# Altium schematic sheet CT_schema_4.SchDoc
size 485 x 464 mm
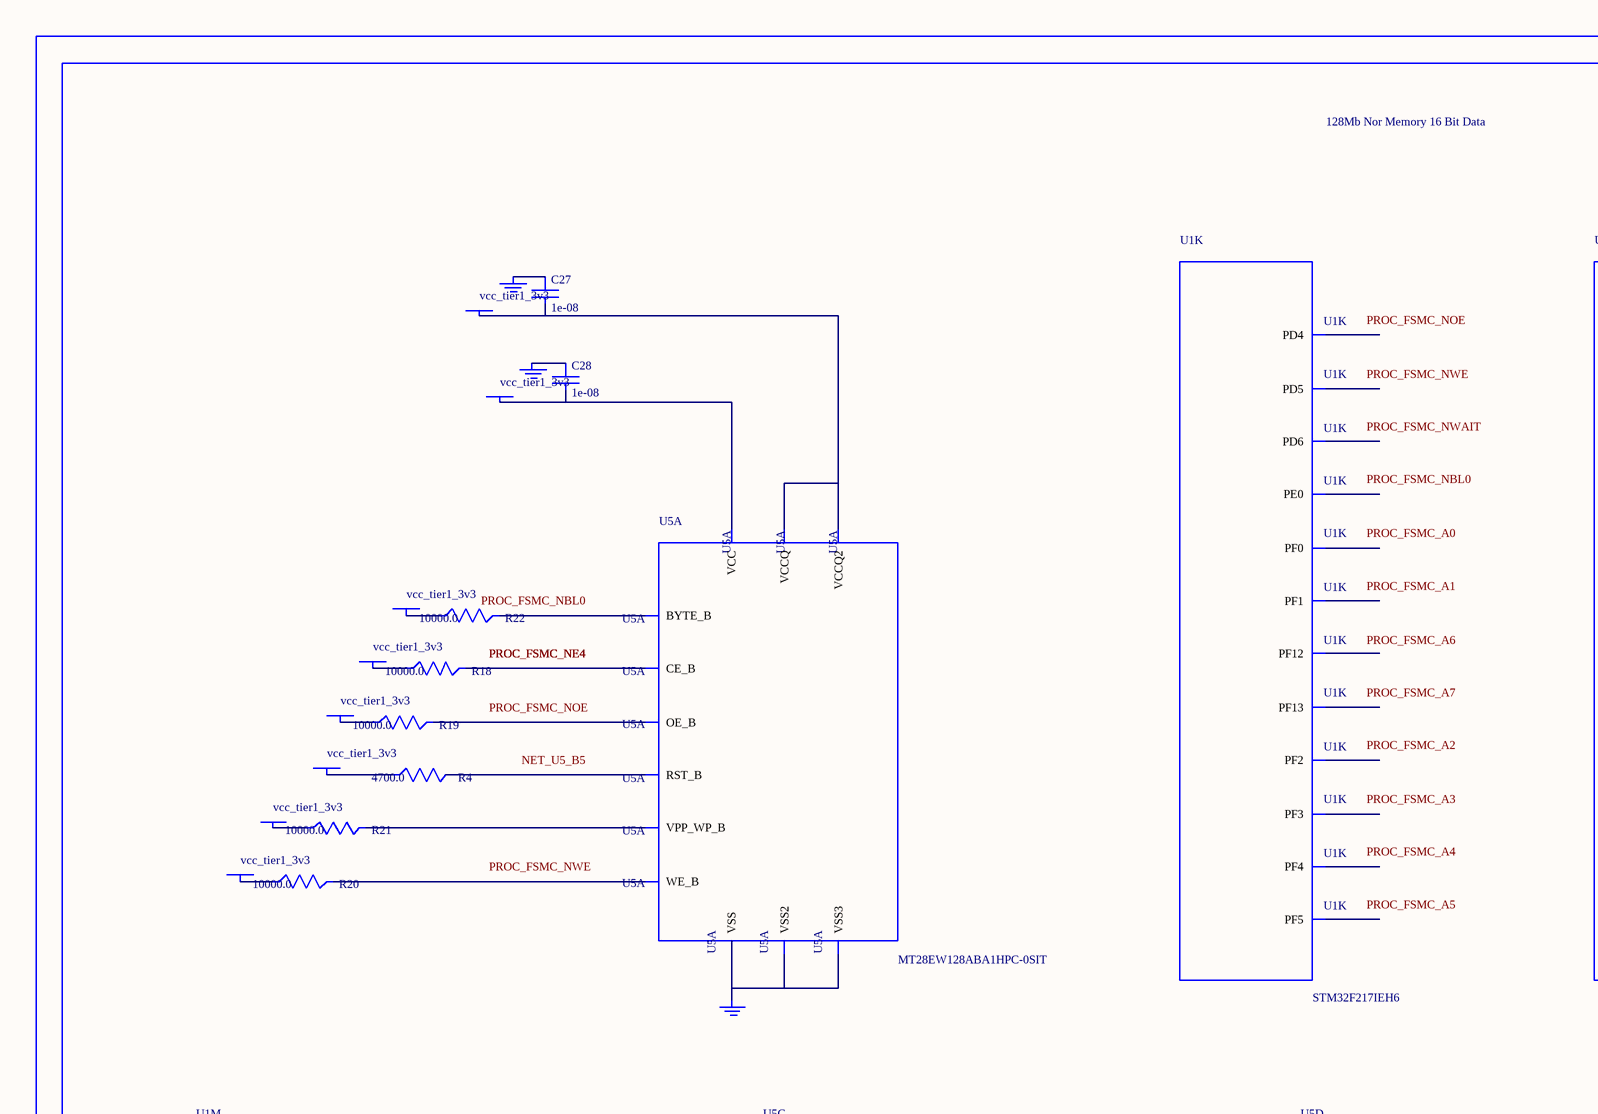
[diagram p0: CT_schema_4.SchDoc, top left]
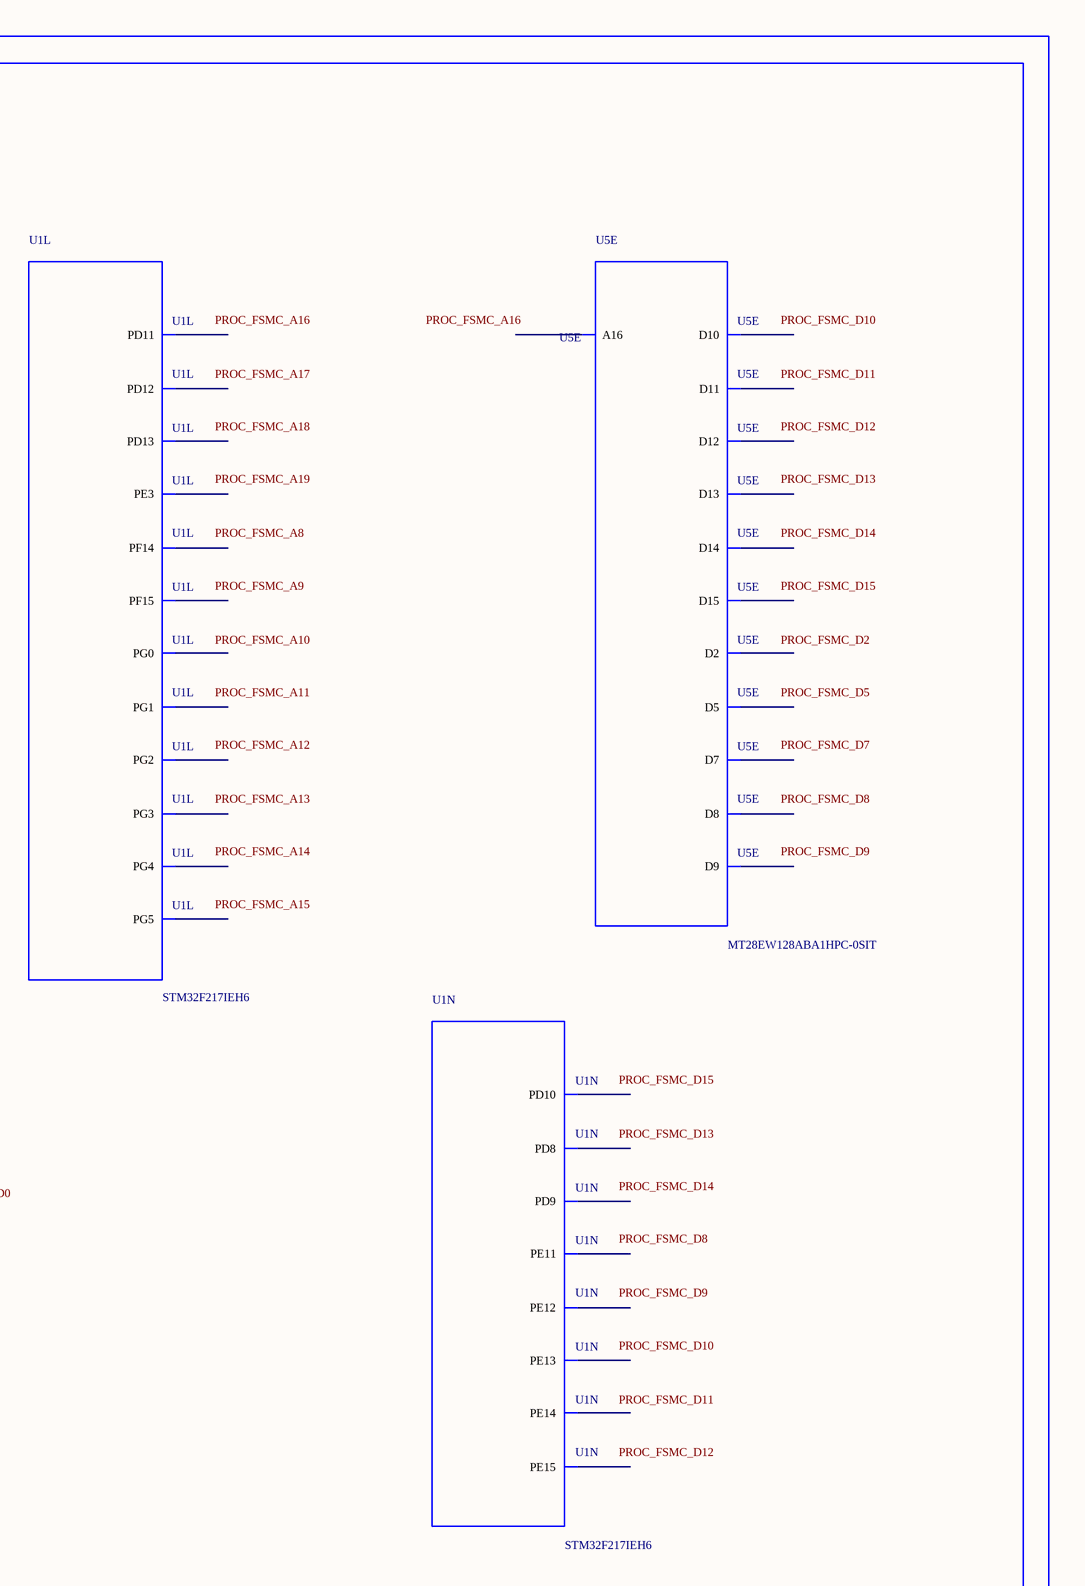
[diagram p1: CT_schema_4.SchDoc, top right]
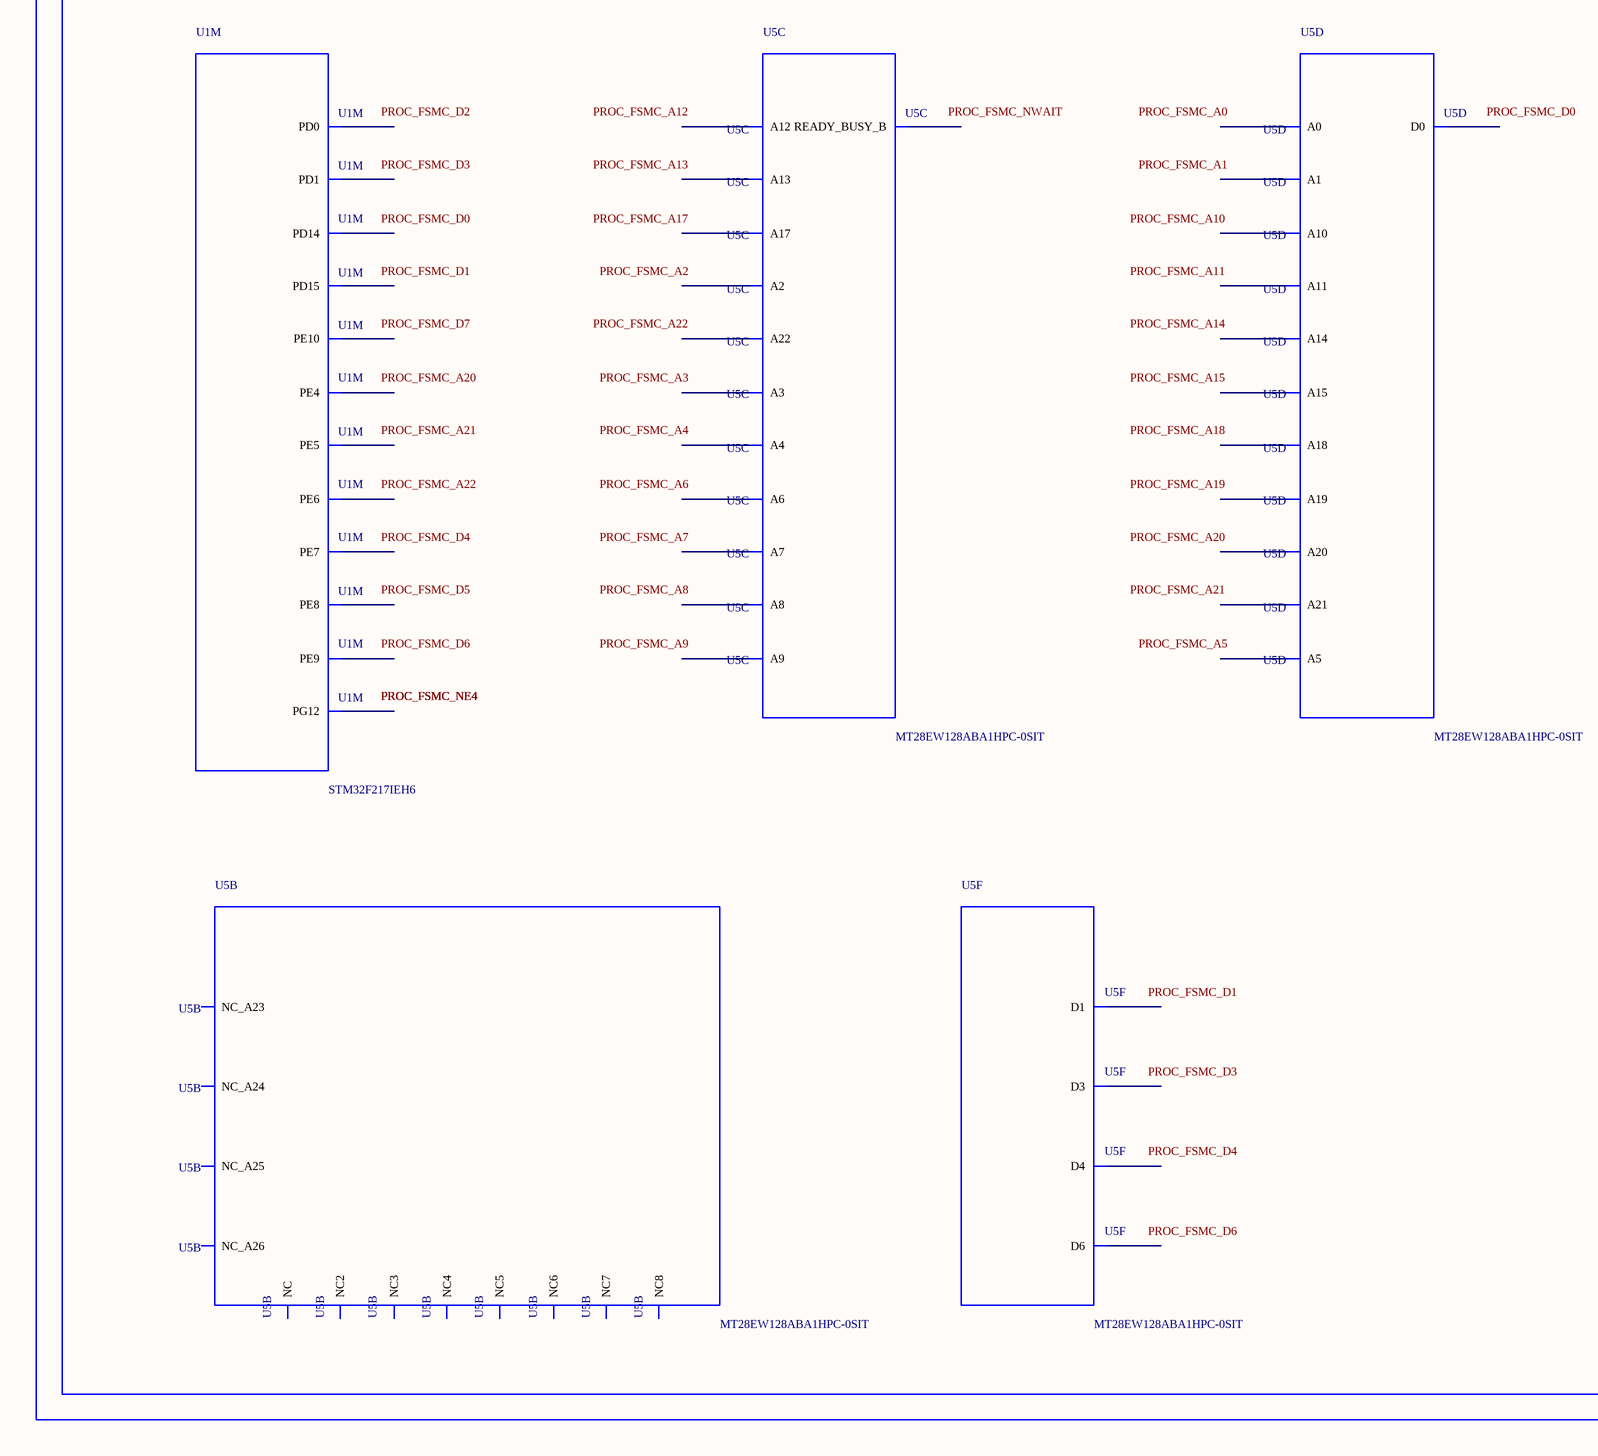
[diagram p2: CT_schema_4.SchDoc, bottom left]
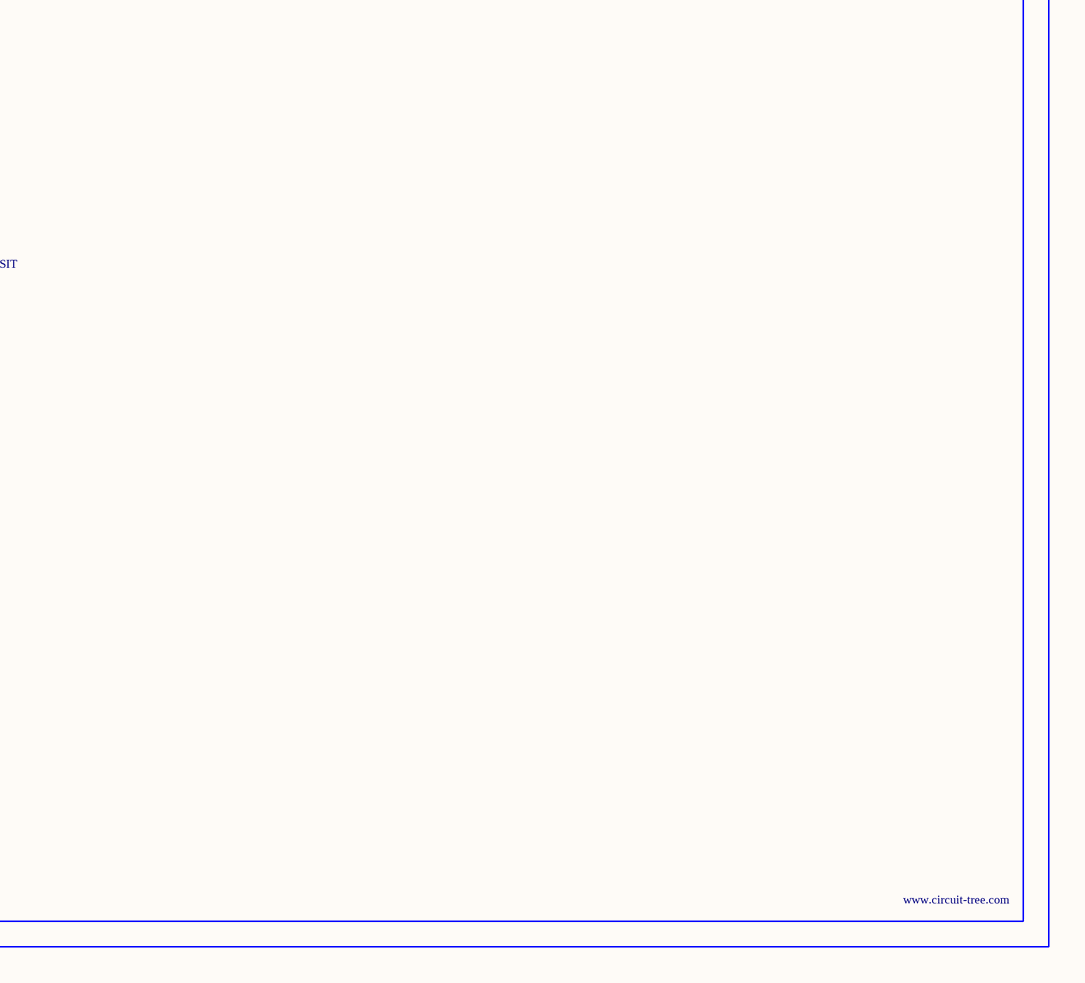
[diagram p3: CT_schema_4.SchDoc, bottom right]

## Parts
BORDER3  (no value)
C27  1e-08  [C0402]
C28  1e-08  [C0402]
GND_INSTANCE_3_0  (no value)
GND_INSTANCE_3_1  (no value)
GND_INSTANCE_3_2  (no value)
POWER_INSTANCE_3_0  vcc_tier1_3v3
POWER_INSTANCE_3_1  vcc_tier1_3v3
POWER_INSTANCE_3_2  vcc_tier1_3v3
POWER_INSTANCE_3_3  vcc_tier1_3v3
POWER_INSTANCE_3_4  vcc_tier1_3v3
POWER_INSTANCE_3_5  vcc_tier1_3v3
POWER_INSTANCE_3_6  vcc_tier1_3v3
POWER_INSTANCE_3_7  vcc_tier1_3v3
R4  4700.0  [R0603]
R18  10000.0  [R0603]
R19  10000.0  [R0603]
R20  10000.0  [R0603]
R21  10000.0  [R0603]
R22  10000.0  [R0603]
U1  STM32F217IEH6  [UFBGA176_25]  (parts K,L,M,N of 14)
U5  MT28EW128ABA1HPC-0SIT  [LBGA-64]  (parts A,B,C,D,E,F of 6)

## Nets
NetC27_1: C27.1 GND_INSTANCE_3_0.0(GND)
NetC27_2: C27.2 POWER_INSTANCE_3_0.0(PWR) U5.D8(VCCQ) U5.F1(VCCQ2)
NetC28_1: C28.1 GND_INSTANCE_3_1.0(GND)
NetC28_2: C28.2 POWER_INSTANCE_3_1.0(PWR) U5.G5(VCC)
NetGND_INSTANCE_3_2_0: GND_INSTANCE_3_2.0(GND) U5.E8(VSS) U5.H2(VSS2) U5.H7(VSS3)
NetPOWER_INSTANCE_3_2_0: POWER_INSTANCE_3_2.0(PWR) R18.1
NetPOWER_INSTANCE_3_3_0: POWER_INSTANCE_3_3.0(PWR) R19.1
NetPOWER_INSTANCE_3_4_0: POWER_INSTANCE_3_4.0(PWR) R20.1
NetPOWER_INSTANCE_3_5_0: POWER_INSTANCE_3_5.0(PWR) R21.1
NetPOWER_INSTANCE_3_6_0: POWER_INSTANCE_3_6.0(PWR) R22.1
NetPOWER_INSTANCE_3_7_0: POWER_INSTANCE_3_7.0(PWR) R4.1
NetR4_2: R4.2 U5.B5(RST_B)
NetR18_2: R18.2 U5.F2(CE_B)
NetR19_2: R19.2 U5.G2(OE_B)
NetR20_2: R20.2 U5.A5(WE_B)
NetR21_2: R21.2 U5.B4(VPP_WP_B)
NetR22_2: R22.2 U5.F7(BYTE_B)

Not connected (* = marked no-connect by the designer): U1 A1(PE3) A4(PE0) B1(PE4) B2(PE5) B3(PE6) B8(PG12) B11(PD6) B12(PD0) C11(PD5) C12(PD1) D10(PD4) E2(PF0) H2(PF2) H3(PF1) J2(PF3) J3(PF4) K3(PF5) K13(PG5) K14(PG4) K15(PG3) L14(PD15) L15(PG2) M7(PG1) M14(PD14) M15(PD13) N6(PF13) N7(PG0) N11(PE13) N13(PD12) N14(PD11) N15(PD10) P6(PF12) P7(PF15) P8(PE8) P9(PE9) P10(PE11) P11(PE14) P14(PD9) P15(PD8) R7(PF14) R8(PE7) R9(PE10) R10(PE12) R11(PE15); U5 A1(NC) A2(A3) A3(A7) A4(READY_BUSY_B) A6(A9) A7(A13) A8(NC2) B1(NC_A26) B2(A4) B3(A17) B6(A8) B7(A12) B8(A22) C1(NC3) C2(A2) C3(A6) C4(A18) C5(A21) C6(A10) C7(A14) C8(NC_A23) D1(NC4) D2(A1) D3(A5) D4(A20) D5(A19) D6(A11) D7(A15) E1(NC5) E2(A0) E3(D0) E4(D2) E5(D5) E6(D7) E7(A16) F3(D8) F4(D10) F5(D12) F6(D14) F8(NC_A24) G1(NC6) G3(D9) G4(D11) G6(D13) G7(D15) G8(NC_A25) H1(NC7) H3(D1) H4(D3) H5(D4) H6(D6) H8(NC8)

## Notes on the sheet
- Labels drawn without touching a wire or pin: NET_U5_B5, PROC_FSMC_A0, PROC_FSMC_A1, PROC_FSMC_A2, PROC_FSMC_A3, PROC_FSMC_A4, PROC_FSMC_A5, PROC_FSMC_A6, PROC_FSMC_A7, PROC_FSMC_A8, PROC_FSMC_A9, PROC_FSMC_A10, PROC_FSMC_A11, PROC_FSMC_A12, PROC_FSMC_A13, PROC_FSMC_A14, PROC_FSMC_A15, PROC_FSMC_A16, PROC_FSMC_A17, PROC_FSMC_A18, PROC_FSMC_A19, PROC_FSMC_A20, PROC_FSMC_A21, PROC_FSMC_A22, PROC_FSMC_D0, PROC_FSMC_D1, PROC_FSMC_D2, PROC_FSMC_D3, PROC_FSMC_D4, PROC_FSMC_D5, PROC_FSMC_D6, PROC_FSMC_D7, PROC_FSMC_D8, PROC_FSMC_D9, PROC_FSMC_D10, PROC_FSMC_D11, PROC_FSMC_D12, PROC_FSMC_D13, PROC_FSMC_D14, PROC_FSMC_D15, PROC_FSMC_NBL0, PROC_FSMC_NOE, PROC_FSMC_NWAIT, PROC_FSMC_NWE

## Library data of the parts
BORDER3 = BORDER_PAGE3
C27 C28 = C0402C103K3RAC
GND_INSTANCE_3_0-GND_INSTANCE_3_2 = GND
POWER_INSTANCE_3_0-POWER_INSTANCE_3_7 = PWR
R4 = RC0603JR-074K7L
R18-R22 = RC0603JR-0710KL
